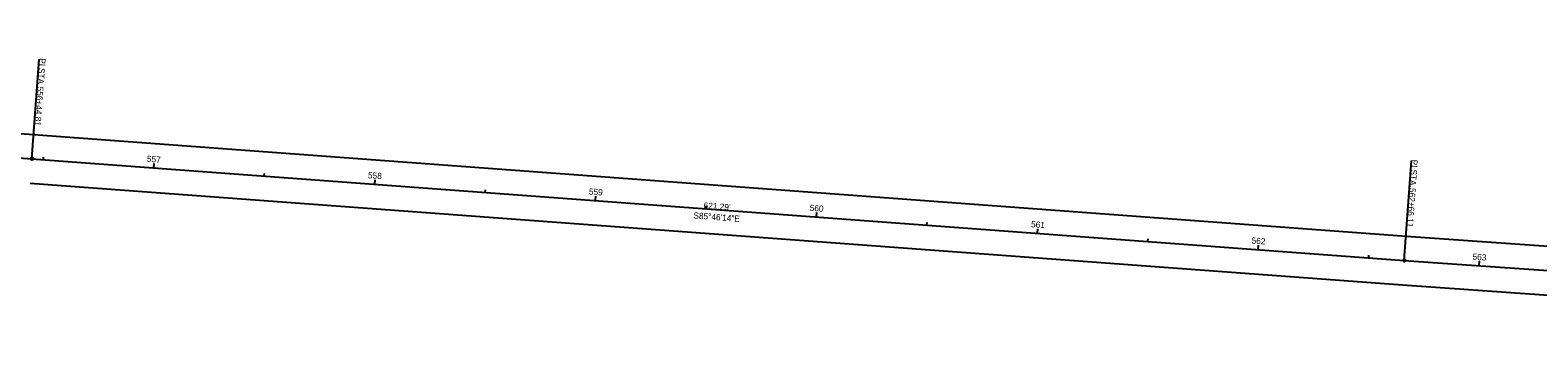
# Model space of a CAD drawing. Extents: x 1898481 to 1901152, y 703119 to 703373.
# Drawn here: x 1899126 to 1899807, y 703192 to 703336 of the extents above; entities that cross this region are included whole.
import ezdxf

# ---------------------------------------------------------------- set-up
doc = ezdxf.new("R2010")
doc.units = 0
for name, color, linetype in [('_CIVIL_CONSTRUCTION', 7, 'Continuous'), ('DT_P_Terrain_Boundary', 7, 'Continuous'), ('DT_P_Triangles', 7, 'Continuous'), ('PF_X_Ground_Line', 7, 'Continuous'), ('PV_P_EOP', 7, 'Continuous'), ('SC_Scratch1', 7, 'Continuous')]:
    doc.layers.add(name, color=color, linetype=linetype)

msp = doc.modelspace()

# ---------------------------------------------------------------- linework, layer by layer
at = {"layer": '_CIVIL_CONSTRUCTION'}
for p, q in [((1899126.72, 703278.32), (1899130.04, 703323.2)), ((1899746.33, 703232.5), (1899749.51, 703277.39))]:
    msp.add_line(p, q, dxfattribs=at)
for centre in [(1899126.72, 703278.32), (1899746.33, 703232.5)]:
    msp.add_circle(centre, 0.6, dxfattribs=at)
at = {"layer": 'DT_P_Triangles'}
for p, q in [((1899131.9, 703277.94), (1899131.98, 703279.14)), ((1899181.76, 703274.25), (1899181.91, 703276.25)), ((1899231.62, 703270.56), (1899231.71, 703271.76)), ((1899281.49, 703266.88), (1899281.63, 703268.87)), ((1899331.35, 703263.19), (1899331.44, 703264.39)), ((1899381.21, 703259.5), (1899381.36, 703261.5)), ((1899431.08, 703255.81), (1899431.17, 703257.01)), ((1899480.94, 703252.13), (1899481.09, 703254.12)), ((1899530.81, 703248.44), (1899530.9, 703249.64)), ((1899580.67, 703244.75), (1899580.82, 703246.75)), ((1899630.53, 703241.06), (1899630.62, 703242.26)), ((1899680.4, 703237.38), (1899680.55, 703239.37)), ((1899730.26, 703233.69), (1899730.35, 703234.89)), ((1899780.13, 703230.1), (1899780.27, 703232.1))]:
    msp.add_line(p, q, dxfattribs=at)
at = {"layer": 'PV_P_EOP'}
for p, q in [((1898484.44, 703336.47), (1899127.53, 703289.29)), ((1899127.53, 703289.29), (1899747.12, 703243.47)), ((1899125.91, 703267.35), (1899745.53, 703221.53)), ((1899747.12, 703243.47), (1900168.38, 703213.58)), ((1899745.53, 703221.53), (1900166.74, 703191.64))]:
    msp.add_line(p, q, dxfattribs=at)
at = {"layer": 'SC_Scratch1'}
for p, q in [((1898483.64, 703325.5), (1899126.72, 703278.32)), ((1899126.72, 703278.32), (1899746.33, 703232.5)), ((1899746.33, 703232.5), (1900167.56, 703202.61))]:
    msp.add_line(p, q, dxfattribs=at)

# ---------------------------------------------------------------- texts
at = {"layer": '_CIVIL_CONSTRUCTION'}
for s, rotation, p in [(' STA. ', 265.77067, (1899129.89, 703320.51)), ('PI', 265.77067, (1899130.14, 703323.89)), ('556+44.81', 265.77067, (1899129.19, 703311.08)), ('PI', 265.94115, (1899749.6, 703278.08)), (' STA. ', 265.94115, (1899749.36, 703274.7)), ('562+66.11', 265.94115, (1899748.69, 703265.27))]:
    msp.add_text(s, height=2.8, rotation=rotation, dxfattribs=at).set_placement(p)
at = {"layer": 'DT_P_Terrain_Boundary'}
msp.add_text("621.29'", height=2.8, rotation=355.77067, dxfattribs=at).set_placement((1899429.87, 703255.95))
at = {"layer": 'DT_P_Triangles'}
for s, rotation, p in [('557', 355.77067, (1899178.54, 703277)), ('558', 355.77067, (1899278.35, 703269.62)), ('559', 355.77067, (1899378.09, 703262.24)), ('560', 355.77067, (1899477.79, 703254.87)), ('561', 355.77067, (1899577.71, 703247.48)), ('562', 355.77067, (1899677.31, 703240.11)), ('563', 355.94115, (1899777.05, 703232.83))]:
    msp.add_text(s, height=2.8, rotation=rotation, dxfattribs=at).set_placement(p)
at = {"layer": 'PF_X_Ground_Line'}
msp.add_text('S85°46\'14"E', height=2.8, rotation=355.77067, dxfattribs=at).set_placement((1899425.26, 703251.43))

doc.saveas('drawing.dxf')
